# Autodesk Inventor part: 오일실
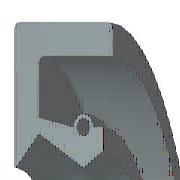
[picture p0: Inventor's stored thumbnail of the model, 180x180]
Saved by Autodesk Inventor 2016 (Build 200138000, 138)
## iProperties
Created: 2015-11
Part Number: 오일실
Material: 고무
Description: 오일-실
Document SubType Name: Modeling
Standard: KS B 2804
Designer: mdu
Standards Organization: KS
Language: ko-KR
Size Designation: D - 10 20 7
Categories: <MemberInstance><Categories><Category DisplayName="샤프트 부품" InternalName="7f7aeb1f-a693-4053-b835-cee3144e0d98" Mnemonic="SHFT"><Category DisplayName="실링" Intern
Density: 0.93 g/cm^3
Mass: 1.11329 g
Surface Area: 16.3871 cm^2
Volume: 1.19708 cm^3
Appearance: 고무 - 검은색 - 버전 1.1
IsCustomPart: 0
Author: mdu
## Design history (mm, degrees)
revolve "본체" stored, may be unused: angle "d17" = 90 deg
revolve "스프링1" stored, may be unused: angle "d18" = 90 deg
body "Solid1"
sketch "스케치1"
  geometry: L1 (0, 10)-(7, 10); L2 (7, 8.25)-(1.75, 8.25); L3 (1.75, 6.75)-(4.9, 5); L4 (4.9, 5)-(0, 5); L5 (0, 0)-(9.586, 0) reference; L6 (4.9, 5)-(6.3, 5.875); L7 (0, 18)-(0, -3) reference; L8 (-1.941, 0)-(11.507, 0) reference; L9 (4.2, 7.1)-(1.75, 7.59); L10 (1.75, 7.59)-(1.75, 8.25); L11 (0, 10)-(0, 5.088); L12 (4.9, 5)-(0, 5); L13 (1.75, 6.75)-(0.152, 5.028); L14 (7, 10)-(7, 8.25); L15 (5.6, 7.1)-(6.3, 7.1); L16 (6.3, 7.1)-(6.3, 5.875); C1 r 0.455 at (4.9, 7.1); A1 r 0.7 centre (4.9, 7.1) between (5.6, 7.1) and (4.2, 7.1); A2 r 0.088 centre (0.088, 5.088) between (0, 5.088) and (0.152, 5.028); 1 further point
  constraints: 28 end point, 5 horizontal alignment, 5 point on line, 4 point on circle, 4 vertical alignment, 3 centre point, 3 tangent, 2 collinear, 2 horizontal, 2 perpendicular, 1 coincident, 1 parallel
  dimensions: "d0" = 20 diameter of L1 L5 (= SD2); "d1" = 1.75 distance of L1.end L2.start (= SD); "d2" = 0.91 diameter of C1 (= SPDI); "d3" = 1.4 diameter of A1 (= SPDA); "d4" = 10 diameter of L3.end L5 (= NND); "d5" = 13.5 diameter of L3.start L5 (= TKDM); "d7" = 15.18 diameter of L9.end L5 (= TKDM + 0.24 x SWDT); "d8" = 1.75 distance between parallel lines of L11 L10 (= SD); "d9" = 4.9 distance from line of L11 C1.centre (= SPDST); "d10" = 14.2 diameter of C1.centre L5 (= HLDM); "d11" = 0.0875 radius of A2 (= 0.25 x LAB); "d12" = 6.3 distance between parallel lines of L11 L16 (= SDI); "d13" = 11.75 diameter of L6.end L5 (= ABDM); "d14" = 7 distance from line of L11 L1.end (= SWDT)
fillet "모깎기1" dims "d6" = 0.3 (= RR)
other parameters: "SD2" = 20 [user parameter; used in 1 equation term], "SWDT" = 7 [user parameter; used in 2 equation terms], "RR" = 0.3 [user parameter; used in 1 equation term], "SD" = 1.75 [user parameter; used in 2 equation terms], "NND" = 10 [user parameter; used in 1 equation term], "SPDA" = 1.4 [user parameter; used in 1 equation term], "SPDI" = 0.91 [user parameter; used in 1 equation term], "TKDM" = 13.5 [user parameter; used in 2 equation terms], "HLDM" = 14.2 [user parameter; used in 1 equation term], "ABDM" = 11.75 [user parameter; used in 1 equation term], "SDI" = 6.3 [user parameter; used in 1 equation term], "SPDST" = 4.9 [user parameter; used in 1 equation term], "LAB" = 0.35 [user parameter; used in 1 equation term], "d15" = 0, "d16" = 0, "d19" = 0
